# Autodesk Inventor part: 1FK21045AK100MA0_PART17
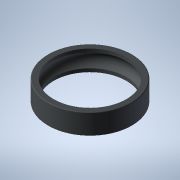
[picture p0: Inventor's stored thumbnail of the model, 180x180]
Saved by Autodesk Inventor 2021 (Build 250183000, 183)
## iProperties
Created: 2025-04
Part Number: 1FK21045AK100MA0_PART17
Material: Generic
Catalog Web Link: www.3dfindit.com
Description: -Servo synchronous motor
Document SubType Name: Modeling
Designer: psAdmin
Mass: 1.64389 g
Surface Area: 26.4305 cm^2
Volume: 1.64389 cm^3
Density: 1 g/cm^3
Appearance: PSOLRGB-212-217-219
Category: PARTsolutions
Title: 1FK21045AK100MA0_PART17
Author: Cadenas PARTsolutions
Comments: Servo synchronous motor
Sending System: PARTsolutions
Preprocessor: ST-DEVELOPER v19.3
PSOL_IDENT_0: {$CADENAS_DATA/23d-libs/siemens_ag/_cat_/e0/5f/1fk21045ak100ma0.prj},216 {VTYP=3D},{NB=1FK21045AK100
PSOL_IDENT_1: MA0_PART17},{LINA=1FK21045AK100MA0_PART17},{NN=1FK21045AK100MA0_PART17},{NOPRJ=TRUE},{DATE=19.08.202
PSOL_IDENT_2: 5 14:01:03},{GEOMDATE=30.07.2025 02:01:57},{VERSION=},{LINEID=10},{WBVAR=},{WBNUMERIC=}  {NB=1FK2104
PSOL_IDENT_3: 5AK100MA0_PART17},{LINA=1FK21045AK100MA0_PART17},{KT=DUMMY},{PREVIEW=../../../_pool_/0f/2c/p_d211_xx
PSOL_IDENT_4: _00438j.png},{DESCSHORT=SIMOTICS S-1FK2 HD, SINAMICS S210 3AC 400V-480V, 1.7 Nm, 6000 rpm},{DESCLONG=
PSOL_IDENT_5: SIMOTICS S-1FK2 HD servo motor M0=2.4 Nm; PN = 1.07 kW at nN=6000 rpm (380-480 V); PN = 0.75 kW at n
PSOL_IDENT_6: N=3000 rpm (200-240 V); with holding brake; degree of protection IP64; cylindrical shaft D19x40mm; a
PSOL_IDENT_7: bsolute encoder 22-bit + 12-bit multiturn (encoder AM22DQC); with OCC interface; plug size M17, rota
PSOL_IDENT_8: table; SIMOTICS S-1FK2 servomotorfor a wide range of uses in industrial environments. SIMOTICS S‑1FK
PSOL_IDENT_9: 2 servomotors are compact synchronous motors with a high dynamic performance that set themselves apa
PSOL_IDENT_10: rt as a result of their high power density, degree of protection and overload capability. The motors
PSOL_IDENT_11: are available in two variants: as High Dynamic variant (highest dynamic performance as a result of
PSOL_IDENT_12: the low intrinsic moment of inertia for applications demanding a high dynamic performance with low m
PSOL_IDENT_13: oved masses) - and as Compact variant (precise and stable closed-loop control for medium up to large
PSOL_IDENT_14: moved masses as a result of a medium intrinsic moment of inertia). SIMOTICSS‑1FK2 servomotors fully
PSOL_IDENT_15: exploit their strengths in a system with the SINAMICSS210 frequency converter and simple connection
PSOL_IDENT_16: using the one cable connection (OCC). Advantages include the short control and positioning times, f
PSOL_IDENT_17: ast and precise correction of disturbing quantities as well as stable control with a high dynamic pe
PSOL_IDENT_18: rformance. The servo motors can be configured to address a wide range of requirements. For example w
PSOL_IDENT_19: ith and without holding brake, IP64 or IP65 degree of protection, singleturn or multiturn absolute e
PSOL_IDENT_20: ncoders - to name just a few. Further, the servomotors are available in different shaft heights exte
PSOL_IDENT_21: nding from 20 to 100. A shaft sealing ring is available to achieve an IP65 degree of protection and
PSOL_IDENT_22: for subsequent mounting at the motor or as spare part. SIMOTICS - the optimum motor for each and eve
PSOL_IDENT_23: ry motion control application.},{INTNO=804766807114},{SUPPLIERALTNO=1FK2104-5AK10-0MA0},{MANUID=1FK2
PSOL_IDENT_24: 1045AK100MA0},{MANUNAME=Siemens},{MANUTYPEDESC=Synchronous motor 1FK2-HD 2,39 Nm},{AAU732=SIMOTICS},
PSOL_IDENT_25: {AAO057=S-1FK2},{AAU734=SIMOTICS S-1FK2 HD servo motor M0=2.4 Nm; PN = 1.07 kW at nN=6000 rpm (380-4
PSOL_IDENT_26: 80 V); PN = 0.75 kW at nN=3000 rpm (200-240 V); with holding brake; degree of protection IP64; cylin
PSOL_IDENT_27: drical shaft D19x40mm; absolute encoder 22-bit + 12-bit multiturn (encoder AM22DQC); with OCC interf
PSOL_IDENT_28: ace; plug size M17, rotatable;},{AAW338=Synchronous motor 1FK2-HD 2,39 Nm},{AAO742=SIMOTICS},{AAO663=
PSOL_IDENT_29: 4042948691236},{NOCUPEROU=1},{PRICEQUANTITY=1},{QUANTITYMIN=1},{QUANTITYINT=1},{CTN=85015100},{COO=D
PSOL_IDENT_30: E},{AAO676=1FK2104-5AK10-0MA0},{AAO677=Siemens AG},{ORDERUNIT=C62},{CONTENTUNIT=C62}
NB: 1FK21045AK100MA0_PART17
NT: Servo synchronous motor
NBSYN: $MANUID._PART17
LINA: 1FK21045AK100MA0_PART17
CATALOG: SIEMENS
PREVIEW: ../../../_pool_/0f/2c/p_d211_xx_00438j.png
DESCSHORT: SIMOTICS S-1FK2 HD, SINAMICS S210 3AC 400V-480V, 1.7 Nm, 6000 rpm
DESCLONG: SIMOTICS S-1FK2 HD servo motor M0=2.4 Nm; PN = 1.07 kW at nN=6000 rpm (380-480 V); PN = 0.75 kW at nN=3000 rpm (200-240 V); with holding brake; degree of protec
INTNO: 804766807114
SUPPLIERALTNO: 1FK2104-5AK10-0MA0
MANUID: 1FK21045AK100MA0
MANUNAME: Siemens
MANUTYPEDESC: Synchronous motor 1FK2-HD 2,39 Nm
AAU732: SIMOTICS
AAO057: S-1FK2
AAU734: SIMOTICS S-1FK2 HD servo motor M0=2.4 Nm; PN = 1.07 kW at nN=6000 rpm (380-480 V); PN = 0.75 kW at nN=3000 rpm (200-240 V); with holding brake; degree of protec
AAW338: Synchronous motor 1FK2-HD 2,39 Nm
AAO742: SIMOTICS
AAO663: 4042948691236.0
NOCUPEROU: 1
PRICEQUANTITY: 1
QUANTITYMIN: 1
QUANTITYINT: 1
CTN: 85015100
COO: DE
ARTICLENO: 1FK21045AK100MA0_PART17
BOMINFO: 1FK21045AK100MA0_PART17
CREATOR: CADENAS GmbH
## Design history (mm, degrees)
feature "2025_04_17_15_45_15_0090"
body "Solid1"
